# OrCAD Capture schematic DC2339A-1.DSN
size C; title: HIGH CURRENT SYNCHRONOUS; rev: 1; note: DEMO CIRCUIT 2339A
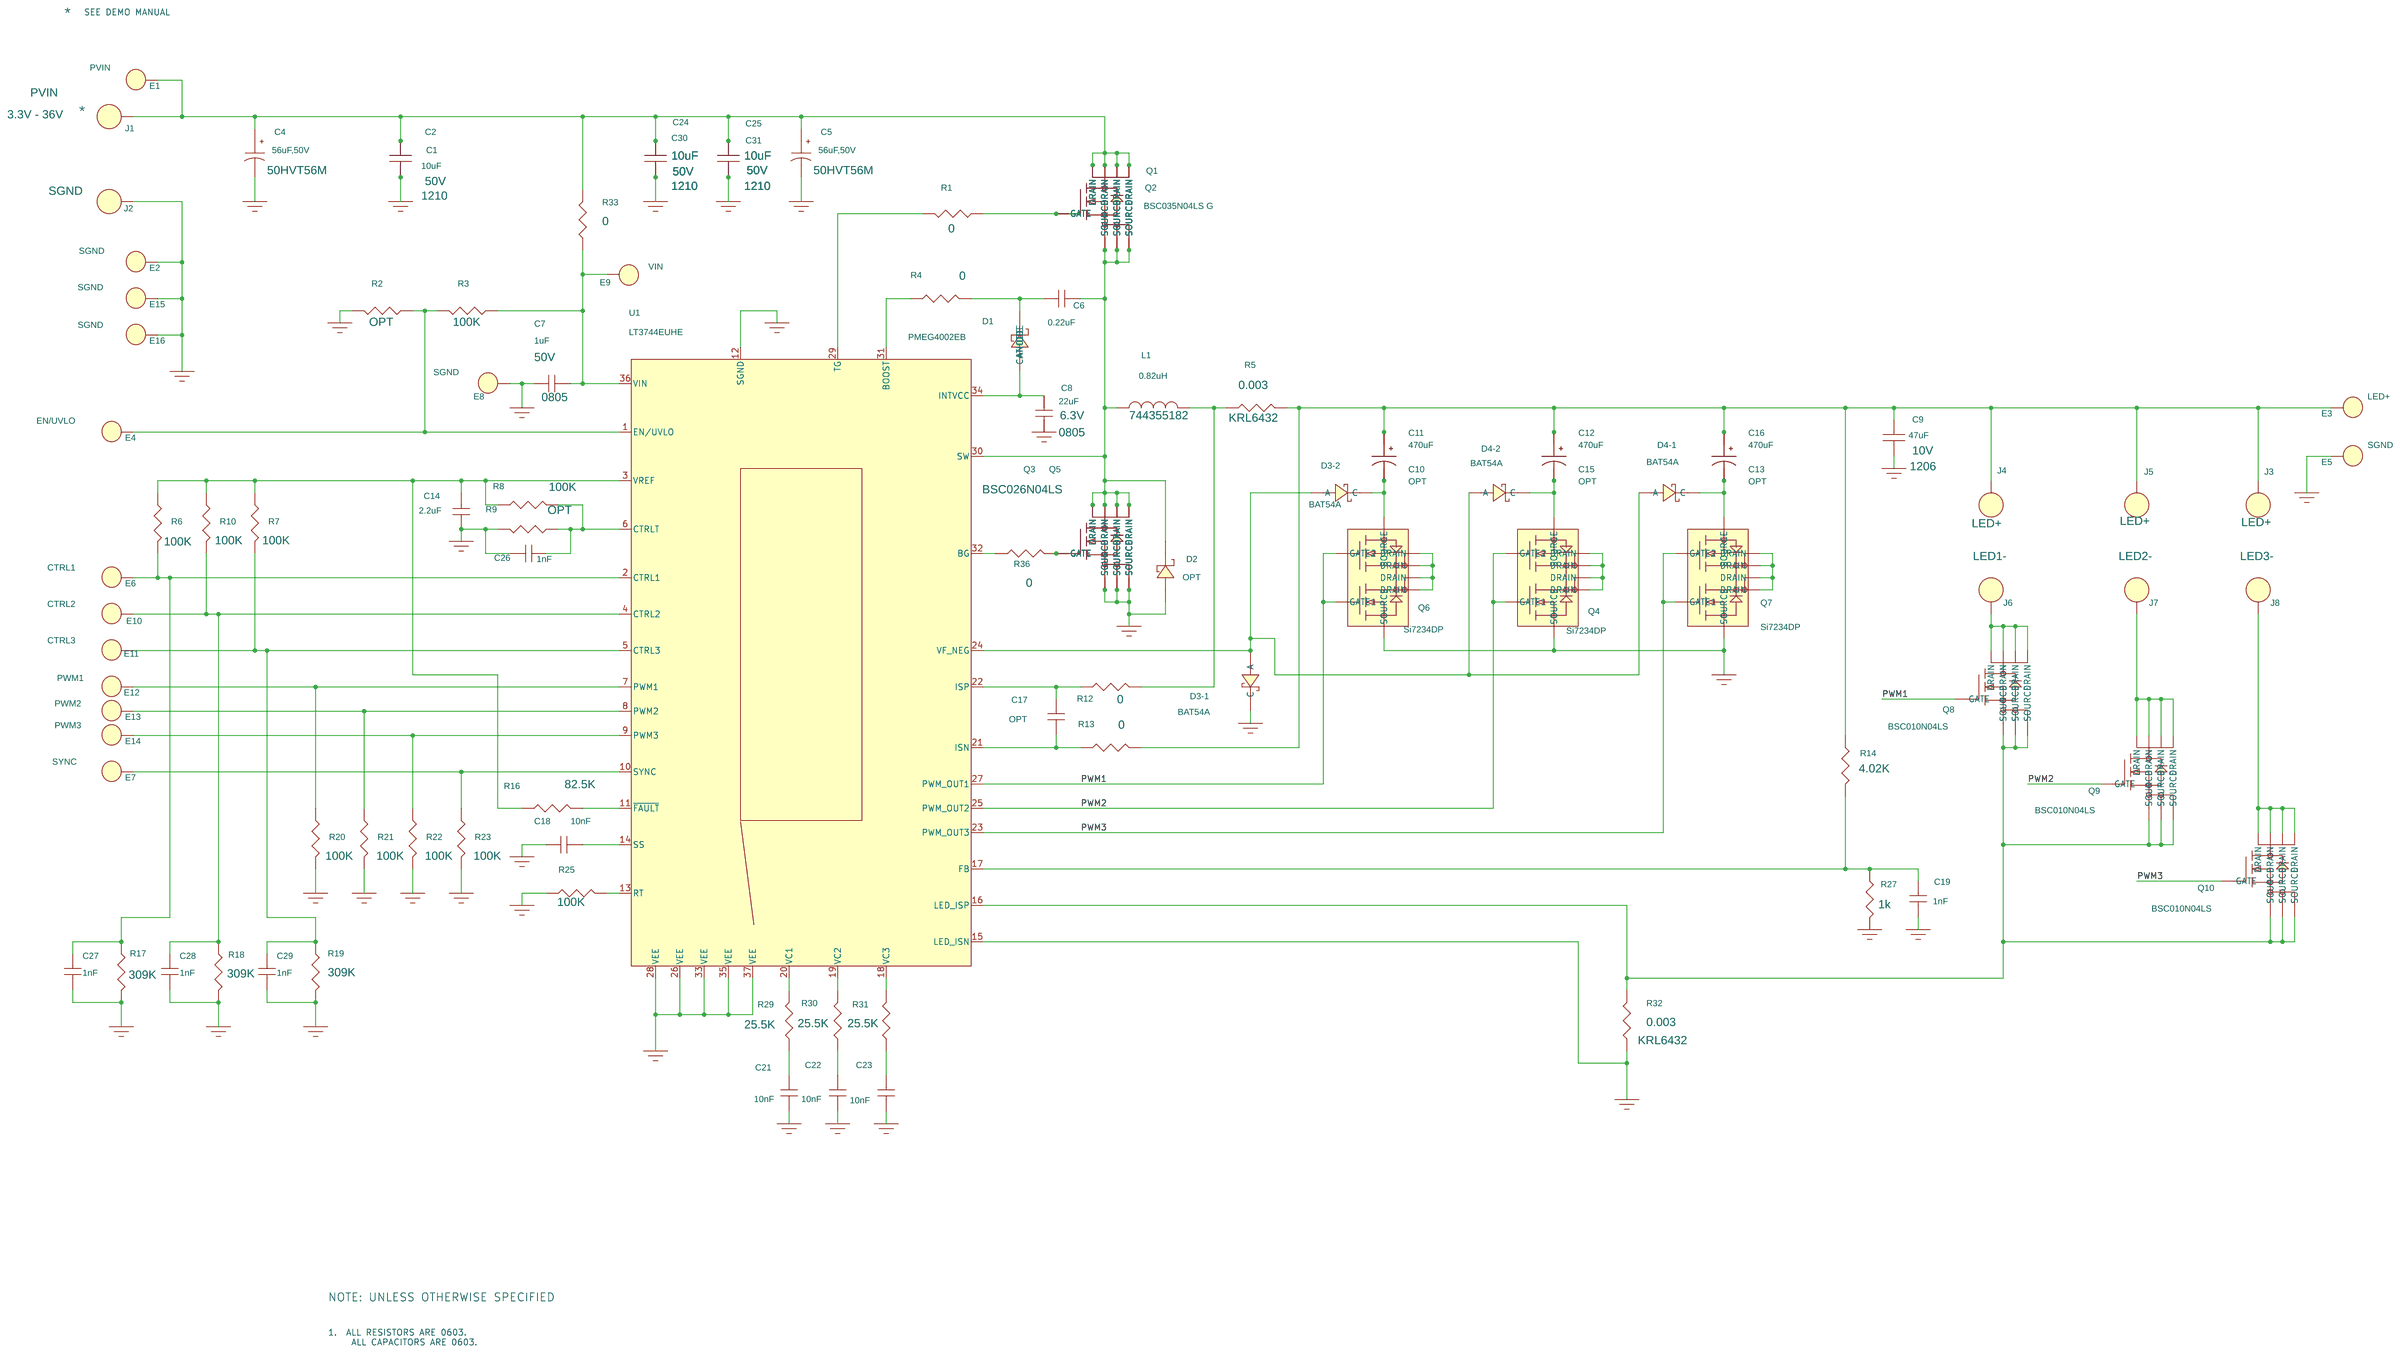
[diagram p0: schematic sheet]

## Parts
C1  10uF  [1210]
C2  10uF  [1210]
C4  56uF,50V  [CAP-HVH-10X10.5]
C5  56uF,50V  [CAP-HVH-10X10.5]
C6  0.22uF  [0603]
C7  1uF  [0805]
C8  22uF  [0805]
C9  47uF  [1206]
C10  OPT  [sanyo-d4d/1210]
C11  470uF  [sanyo-d4d/1210]
C12  470uF  [sanyo-d4d/1210]
C13  OPT  [sanyo-d4d/1210]
C14  2.2uF  [0603]
C15  OPT  [sanyo-d4d/1210]
C16  470uF  [sanyo-d4d/1210]
C17  OPT  [0603]
C18  10nF  [0603]
C19  1nF  [0603]
C21  10nF  [0603]
C22  10nF  [0603]
C23  10nF  [0603]
C24  10uF  [1210]
C25  10uF  [1210]
C26  1nF  [0603]
C27  1nF  [0603]
C28  1nF  [0603]
C29  1nF  [0603]
C30  10uF  [1210]
C31  10uF  [1210]
D1  PMEG4002EB  [SOD523]
D2  OPT  [DI123]
D3  BAT54A  [SOT23]  (sections -1,-2)
D4  BAT54A  [SOT23]  (sections -1,-2)
E1  TURRETS  [MILLMAX-2501-2]
E2  TURRETS  [MILLMAX-2501-2]
E3  TURRETS  [MILLMAX-2501-2]
E4  TURRETS  [MILLMAX-2501-2]
E5  TURRETS  [MILLMAX-2501-2]
E6  TURRETS  [MILLMAX-2501-2]
E7  TURRETS  [MILLMAX-2501-2]
E8  TURRETS  [MILLMAX-2501-2]
E9  TURRETS  [MILLMAX-2501-2]
E10  TURRETS  [MILLMAX-2501-2]
E11  TURRETS  [MILLMAX-2501-2]
E12  TURRETS  [MILLMAX-2501-2]
E13  TURRETS  [MILLMAX-2501-2]
E14  TURRETS  [MILLMAX-2501-2]
E15  TURRETS  [MILLMAX-2501-2]
E16  TURRETS  [MILLMAX-2501-2]
J1  BANANA JACK  [KEY-575-4]
J2  BANANA JACK  [KEY-575-4]
J3  BANANA JACK  [KEY-575-4]
J4  BANANA JACK  [KEY-575-4]
J5  BANANA JACK  [KEY-575-4]
J6  BANANA JACK  [KEY-575-4]
J7  BANANA JACK  [KEY-575-4]
J8  BANANA JACK  [KEY-575-4]
L1  0.82uH  [IND-744355047]
Q1  BSC035N04LS G  [LFPAK/SO]
Q2  BSC035N04LS G  [LFPAK/SO]
Q3  BSC026N04LS  [LFPAK/SO]
Q4  Si7234DP  [LFPAK/SO]
Q5  BSC026N04LS  [LFPAK/SO]
Q6  Si7234DP  [LFPAK/SO]
Q7  Si7234DP  [LFPAK/SO]
Q8  BSC010N04LS  [LFPAK/SO]
Q9  BSC010N04LS  [LFPAK/SO]
Q10  BSC010N04LS  [LFPAK/SO]
R1  0  [0603]
R2  OPT  [0603]
R3  100K  [0603]
R4  0  [0603]
R5  0.003  [RES-KRL6432]
R6  100K  [0603]
R7  100K  [0603]
R8  100K  [0603]
R9  OPT  [0603]
R10  100K  [0603]
R12  0  [0603]
R13  0  [0603]
R14  4.02K  [0603]
R16  82.5K  [0603]
R17  309K  [0603]
R18  309K  [0603]
R19  309K  [0603]
R20  100K  [0603]
R21  100K  [0603]
R22  100K  [0603]
R23  100K  [0603]
R25  100K  [0603]
R27  1k  [0603]
R29  25.5K  [0603]
R30  25.5K  [0603]
R31  25.5K  [0603]
R32  0.003  [RES-KRL6432]
R33  0  [0603]
R36  0  [0603]
U1  LT3744EUHE  [QFN-36-5X6-UHE-1876-REV-0]

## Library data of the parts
C1 C2 C24 C25 C30 C31 = EMK212BJ475MG: 1st Part Field: 50V
C4 C5 = 4TPE220MF: 1st Part Field: 50V; 4th Part Field: 50HVT56M; 5th Part Field: 2R5TPE330M9
C6 C14 C17-C19 C21-C23 C26-C29 = 06033C104KAT2A
C7 = 06033C104KAT2A: 1st Part Field: 50V
C8 = 06033C104KAT2A: 1st Part Field: 6.3V
C9 = EMK212BJ475MG: 1st Part Field: 10V
C10-C13 C15 C16 = CAPACITOR_POL
D1 = DIODE_SCHOTTKY_1
D2 = DIODE_SCHOTTKY
D3 D4 = BAT54A_2
E1 = TURRETS_1: Label: PVIN; Manufacturer P/N: 2308-2; Vendor: Digikey; Vendor P/N: 2308-2
E2 E8 E15 E16 = TURRETS_1: Label: SGND; Manufacturer P/N: 2308-2; Vendor: Digikey; Vendor P/N: 2308-2
E3 = TURRETS_1: Label: LED+; Manufacturer P/N: 2308-2; Vendor: Digikey; Vendor P/N: 5V Clamp; Volts/Watts: *
E4 = TURRETS_1: Label: EN/UVLO; Manufacturer P/N: 2308-2; Vendor: Digikey; Vendor P/N: 2308-2
E5 = TURRETS_1: Label: SGND; Manufacturer P/N: 2308-2; Vendor: Digikey; Vendor P/N: 5V Clamp; Volts/Watts: *
E6 = TURRETS_1: Label: CTRL1; Manufacturer P/N: 2308-2; Vendor: Digikey; Vendor P/N: 2308-2
E7 = TURRETS_1: Label: SYNC; Manufacturer P/N: 2308-2; Vendor: Digikey; Vendor P/N: 2308-2
E9 = TURRETS_1: Label: VIN; Manufacturer P/N: 2308-2; Vendor: Digikey; Vendor P/N: 2308-2
E10 = TURRETS_1: Label: CTRL2; Manufacturer P/N: 2308-2; Vendor: Digikey; Vendor P/N: 2308-2
E11 = TURRETS_1: Label: CTRL3; Manufacturer P/N: 2308-2; Vendor: Digikey; Vendor P/N: 2308-2
E12 = TURRETS_1: Label: PWM1; Manufacturer P/N: 2308-2; Vendor: Digikey; Vendor P/N: 2308-2
E13 = TURRETS_1: Label: PWM2; Manufacturer P/N: 2308-2; Vendor: Digikey; Vendor P/N: 2308-2
E14 = TURRETS_1: Label: PWM3; Manufacturer P/N: 2308-2; Vendor: Digikey; Vendor P/N: 2308-2
J1 = BANANA-JACK: 1ST PART FIELD: 3.3V - 36V; 3RD PART FIELD: PVIN
J2 = BANANA-JACK: 3RD PART FIELD: SGND
J3-J5 = BANANA-JACK: 3RD PART FIELD: LED+
J6 = BANANA-JACK: 3RD PART FIELD: LED1-
J7 = BANANA-JACK: 3RD PART FIELD: LED2-
J8 = BANANA-JACK: 3RD PART FIELD: LED3-
L1 = INDUCTOR: 5th Part Field: 744355182
Q1-Q3 Q5 Q8-Q10 = 2N7000_4
Q4 Q6 Q7 = 2N7000_3
R1-R4 R6-R10 R12-R14 R16-R23 R25 R27 R29-R31 R33 R36 = CJ06-000M
R5 R32 = CJ06-000M: 1st Part Field: 3W; 2nd Part Field: KRL6432; 4th Part Field: SUSUMU; 5th Part Field: KRL6432E-M-R003-F
U1 = LT3743EUF_37

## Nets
GND: C1.2 C2.2 C4.2 C5.2 C7.1 C8.2 C9.2 C14.1 C18.1 C19.2 C21.2 C22.2 C23.2 C24.2 C25.2 C26.2 C27.2 C28.2 C29.2 C30.2 C31.2 D2.1(ANODE) D3.1(C) E2.1(TP) E5.1(TP) E8.1(TP) E15.1(TP) E16.1(TP) J2.1 Q3.1(SOURCE) Q3.2(SOURCE) Q3.3(SOURCE) Q4.3(SOURCE) Q5.1(SOURCE) Q5.2(SOURCE) Q5.3(SOURCE) Q6.3(SOURCE) Q7.3(SOURCE) R2.1 R9.1 R17.1 R18.1 R19.1 R20.1 R21.1 R22.1 R23.1 R25.2 R27.1 R32.2 U1.12(SGND) U1.15(LED_ISN) U1.26(VEE) U1.28(VEE) U1.33(VEE) U1.35(VEE) U1.37(VEE)
PWM1: Q6.2(GATE2) Q6.4(GATE1) Q8.4(GATE) U1.27(PWM_OUT1)
PWM2: Q4.2(GATE2) Q4.4(GATE1) Q9.4(GATE) U1.25(PWM_OUT2)
PWM3: Q7.2(GATE2) Q7.4(GATE1) Q10.4(GATE) U1.23(PWM_OUT3)
N17675432: E4.1(TP) R2.2 R3.1 U1.1(EN/UVLO)
N17676190: C7.2 E9.1(TP) R3.2 R33.2 U1.36(VIN)
N17680723: C27.1 E6.1(TP) R6.1 R17.2 U1.2(CTRL1)
N17680759: C28.1 E10.1(TP) R10.1 R18.2 U1.4(CTRL2)
N17680841: E13.1(TP) R21.2 U1.8(PWM2)
N17682572: C29.1 E11.1(TP) R7.1 R19.2 U1.5(CTRL3)
N17684664: R1.1 U1.29(TG)
N17686510: C1.1 C2.1 C4.1 C5.1 C24.1 C25.1 C30.1 C31.1 E1.1(TP) J1.1 Q1.5(DRAIN) Q1.6(DRAIN) Q1.7(DRAIN) Q1.8(DRAIN) Q2.5(DRAIN) Q2.6(DRAIN) Q2.7(DRAIN) Q2.8(DRAIN) R33.1
N17686596: C6.2 D2.2(CATHODE) L1.1 Q1.1(SOURCE) Q1.2(SOURCE) Q1.3(SOURCE) Q2.1(SOURCE) Q2.2(SOURCE) Q2.3(SOURCE) Q3.5(DRAIN) Q3.6(DRAIN) Q3.7(DRAIN) Q3.8(DRAIN) Q5.5(DRAIN) Q5.6(DRAIN) Q5.7(DRAIN) Q5.8(DRAIN) U1.30(SW)
N17687211: C8.1 D1.1(ANODE) U1.34(INTVCC)
N17691071: C17.1 R12.2 U1.22(ISP)
N17691129: L1.2 R5.2 R12.1
N17691497: C9.1 C10.1 C11.1 C12.1 C13.1 C15.1 C16.1 E3.1(TP) J3.1 J4.1 J5.1 R5.1 R13.1 R14.2
N17691505: C17.2 R13.2 U1.21(ISN)
N17693878: C19.1 R14.1 R27.2 U1.17(FB)
N17698032: C26.1 R8.1 R9.2 U1.6(CTRLT)
N17698069: C14.2 R6.2 R7.2 R8.2 R10.2 R16.2 U1.3(VREF)
N17699714: E12.1(TP) R20.2 U1.7(PWM1)
N17704639: R4.2 U1.31(BOOST)
N17719154: Q1.4(GATE) Q2.4(GATE) R1.2
N17721353: Q6.5(DRAIN) Q6.6(DRAIN) Q6.7(DRAIN) Q6.8(DRAIN)
N17721800: Q4.5(DRAIN) Q4.6(DRAIN) Q4.7(DRAIN) Q4.8(DRAIN)
N17754148: C10.2 C11.2 D3.2(C) Q6.1(SOURCE)
N17754505: C12.2 C15.2 D4.2(C) Q4.1(SOURCE)
N17759565: C6.1 D1.2(CATHODE) R4.1
N17785411: C18.2 U1.14(SS)
N17785696: R25.1 U1.13(RT)
N17787930: E14.1(TP) R22.2 U1.9(PWM3)
N17789094: E7.1(TP) R23.2 U1.10(SYNC)
N17790231: R16.1 U1.11(~{FAULT})
N17850832: Q7.5(DRAIN) Q7.6(DRAIN) Q7.7(DRAIN) Q7.8(DRAIN)
N17868454: C22.1 R30.2
N17868756: C21.1 R29.2
N17870260: C23.1 R31.2
N17930459: R29.1 U1.20(VC1)
N17930761: R30.1 U1.19(VC2)
N17931065: R31.1 U1.18(VC3)
N17934745: Q8.1(SOURCE) Q8.2(SOURCE) Q8.3(SOURCE) Q9.1(SOURCE) Q9.2(SOURCE) Q9.3(SOURCE) Q10.1(SOURCE) Q10.2(SOURCE) Q10.3(SOURCE) R32.1 U1.16(LED_ISP)
N17953225: J6.1 Q8.5(DRAIN) Q8.6(DRAIN) Q8.7(DRAIN) Q8.8(DRAIN)
N17955263: J7.1 Q9.5(DRAIN) Q9.6(DRAIN) Q9.7(DRAIN) Q9.8(DRAIN)
N17960031: J8.1 Q10.5(DRAIN) Q10.6(DRAIN) Q10.7(DRAIN) Q10.8(DRAIN)
N18058381: C13.2 C16.2 D4.1(C) Q7.1(SOURCE)
N18072402: D3.3(A) D4.3(A) U1.24(VF_NEG)
N18181889: R36.2 U1.32(BG)
N18294124: Q3.4(GATE) Q5.4(GATE) R36.1

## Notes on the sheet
- *
- SEE DEMO MANUAL
- *
- NOTE: UNLESS OTHERWISE SPECIFIED
- 1.  ALL RESISTORS ARE 0603.
       ALL CAPACITORS ARE 0603.
